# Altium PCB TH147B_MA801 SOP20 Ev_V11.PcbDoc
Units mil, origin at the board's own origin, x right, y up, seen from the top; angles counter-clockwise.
Board outline 2850 x 2110 mil, 2 copper layers (Top Layer, Bottom Layer); 44 components, 39 nets, 228 pads, 77 vias.
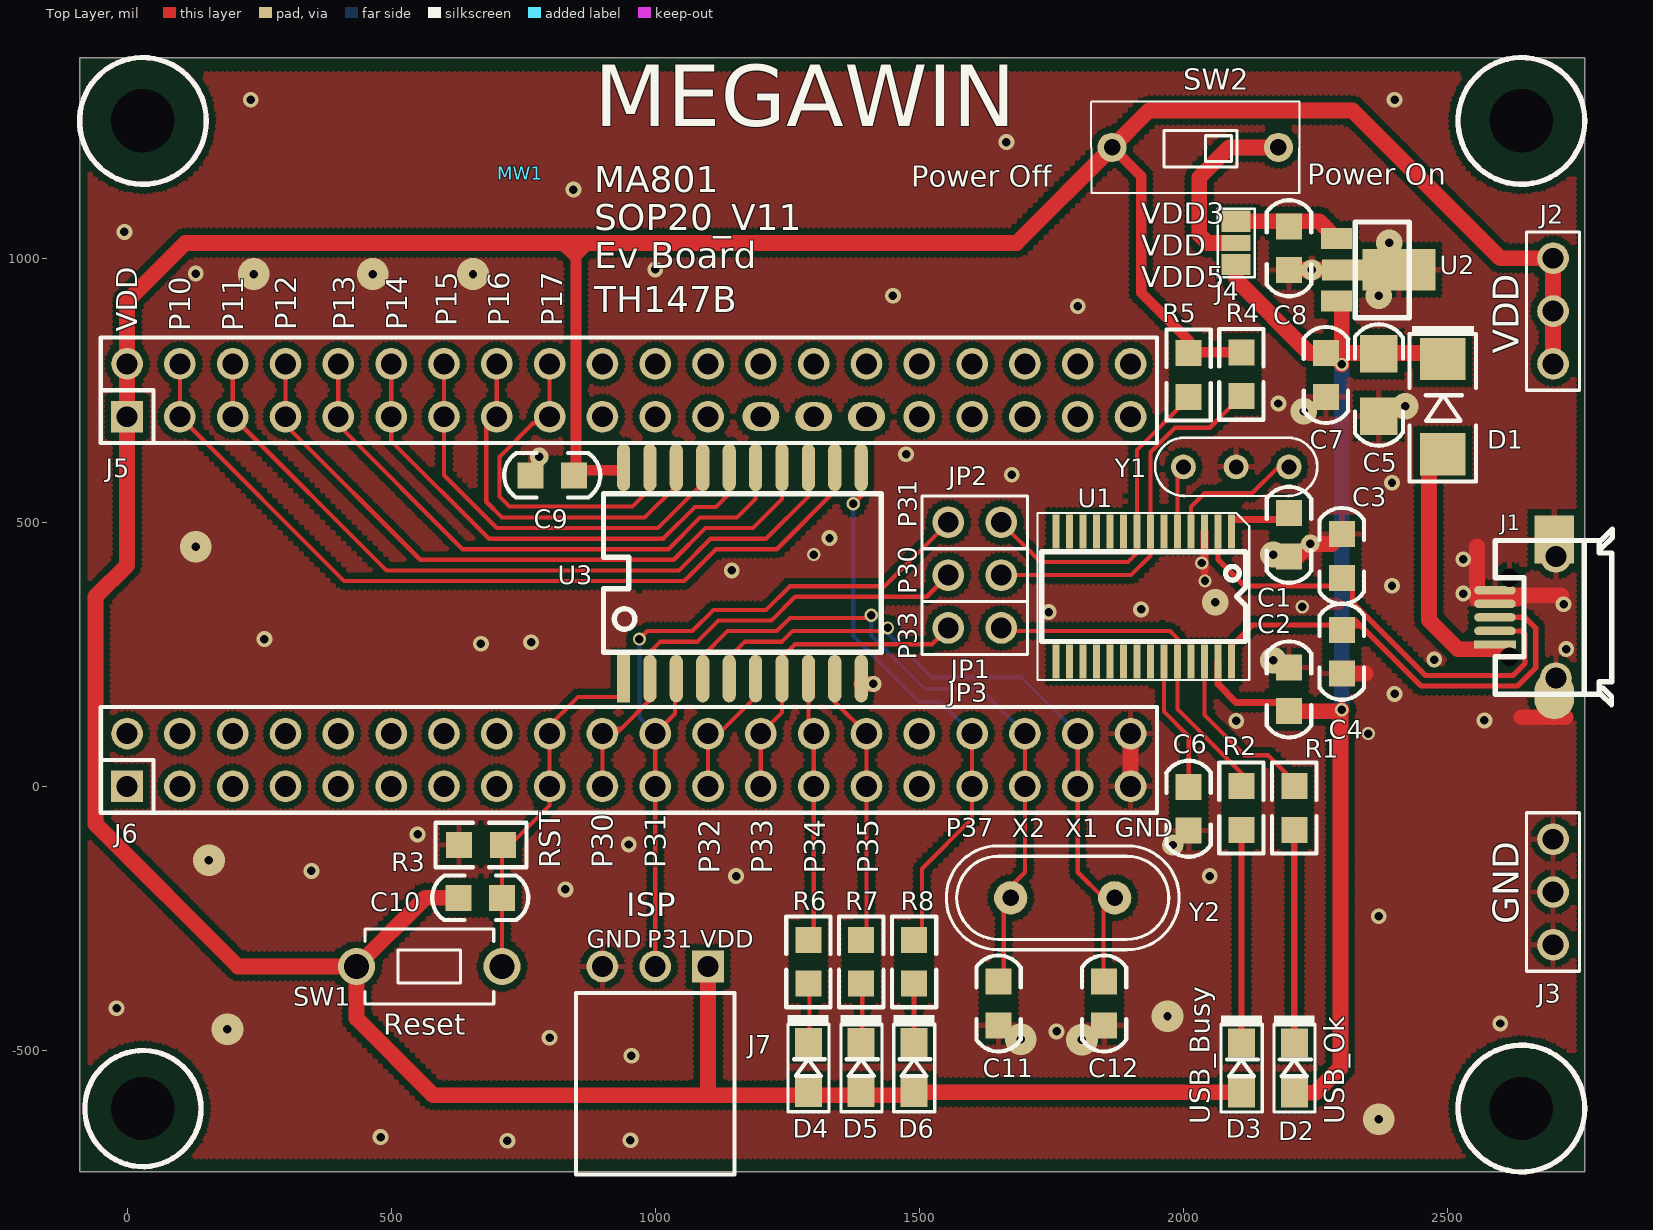
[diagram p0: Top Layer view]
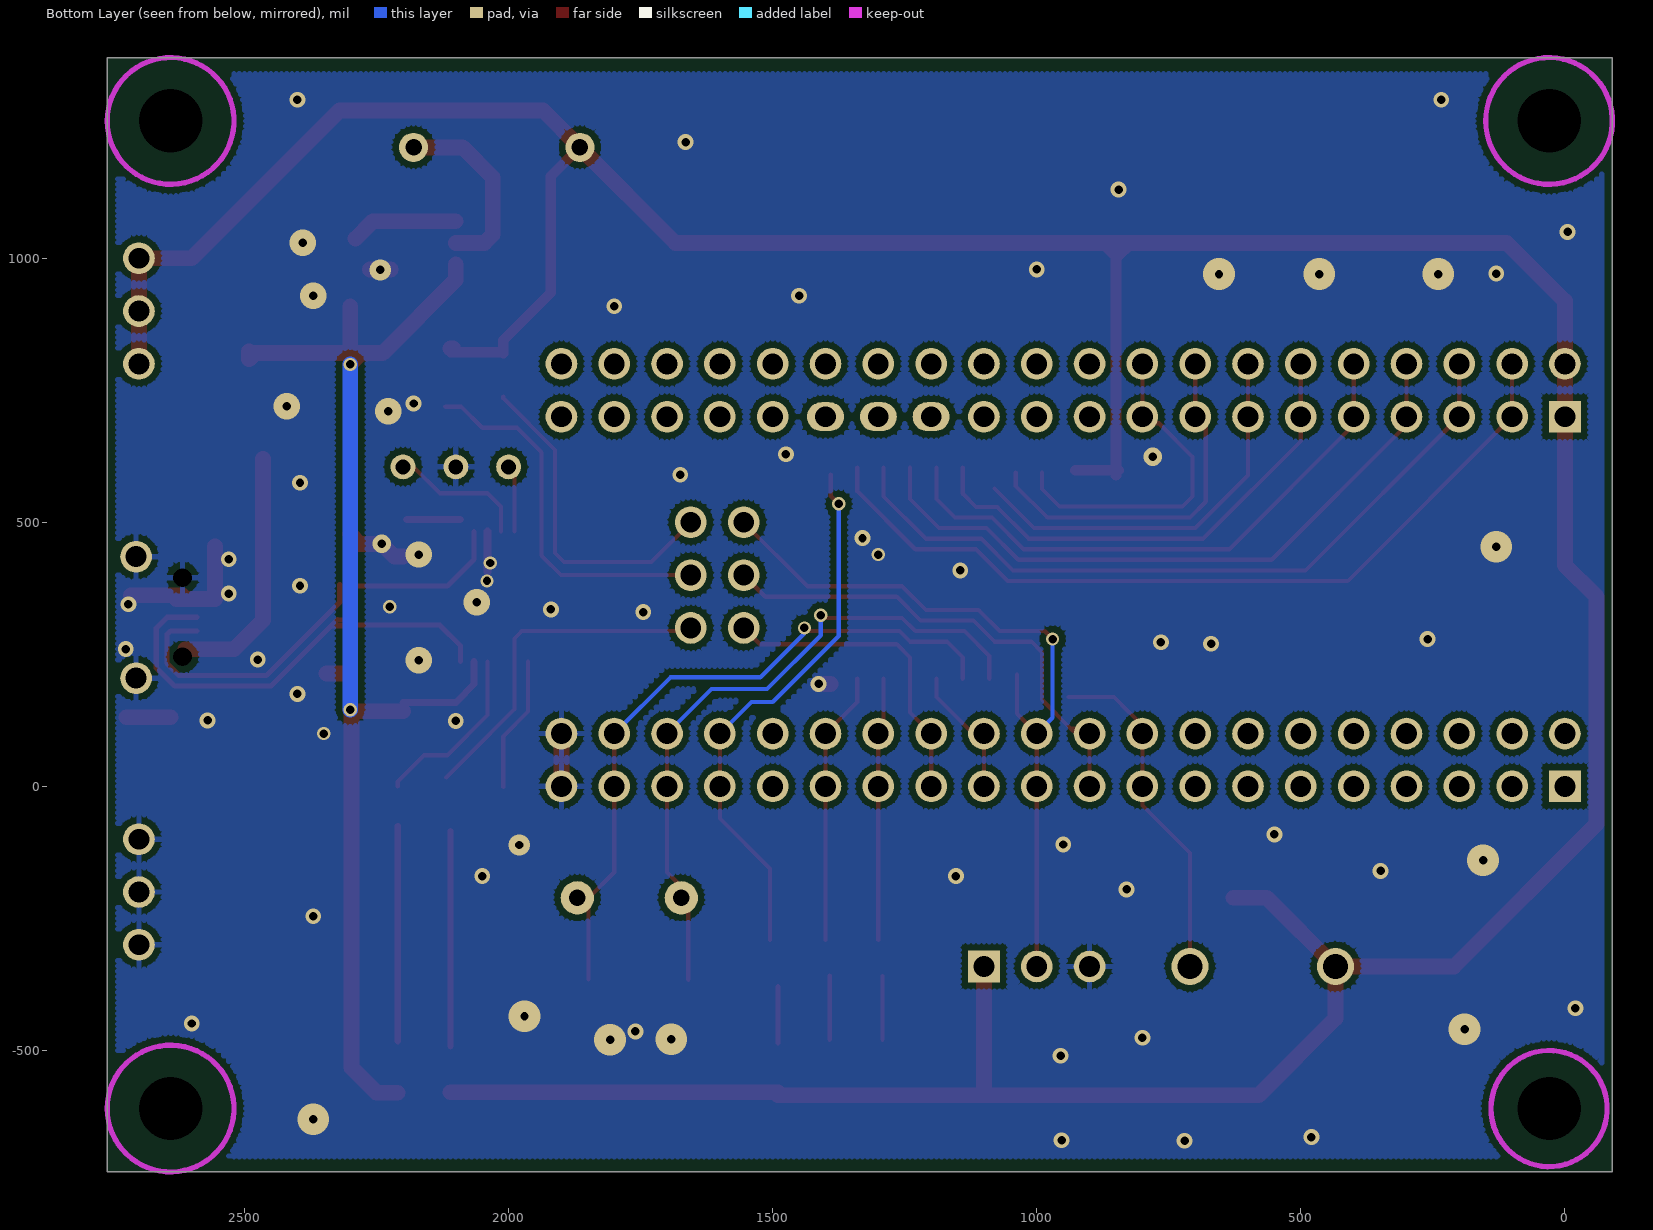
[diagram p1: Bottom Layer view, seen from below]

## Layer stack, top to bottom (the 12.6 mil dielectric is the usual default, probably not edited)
Top Layer: signal copper 1.4
Dielectric: dielectric 12.6, FR-4, Dk 4.8
Bottom Layer: signal copper 1.4

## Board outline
-90,-730 -90,1380 2760,1380 2760,-730

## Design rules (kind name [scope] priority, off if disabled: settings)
Clearance 12 [All] p1 off: gap=12
Clearance 10 [All] p2 off: gap=10
Clearance 6 [All] p3: gap=6
ComponentClearance [All] p1 off: gap=10 collisioncheckmode=3 verticalgap=10 showdistances=FALSE
HoleSize [All] p1: absolutevalues=TRUE maxlimit=500 minlimit=1 maxpercent=80.000 minpercent=20.000
MinimumSolderMaskSliver [All] p1 off: minsoldermaskwidth=10
PolygonConnect VIA [ISVIA] p1: connectstyle=Direct reliefconductorwidth=10 reliefentries=4 polygonreliefangle="90 Angle"
PolygonConnect [All] p2: connectstyle=Relief reliefconductorwidth=10 reliefentries=4 polygonreliefangle="90 Angle"
RoutingVias [All] p1: holewidth=16 width=25 viastyle="Through Hole" minholewidth=16 minwidth=24 maxholewidth=28 maxwidth=50
SilkToSilkClearance [All] p1 off: silktosilkclearance=10
SilkscreenOverComponentPads [All] p1 off: minsilkscreentomaskgap=10
SolderMaskExpansion [All] p1 off: expansion=4
Width [All] p1: maxlimit=200 minlimit=6 preferedwidth=10
23 further rules are at their usual default settings.

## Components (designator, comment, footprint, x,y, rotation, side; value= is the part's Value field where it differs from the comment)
C1 "4.7uF" 0805C 2200,476.34 r270 top
C2 "0.1uF" 0805C 2200,183.66 r270 top
C3 "15pF" 0805C 2300,436.34 r90 top
C4 "15pF" 0805C 2300,255 r270 top
C5 "4.7uF" 1206C 2370,760 r270 top
C6 "0.1uF" 0805C 2010,-42.34 r90 top
C7 "0.1uF" 0805C 2270,779 r270 top
C8 "4.7uF" 0805C 2200,1019 r270 top
C9 "0.1uF" 0805C 805,589 r180 top
C10 "1u" 0805C 668.66,-211 r0 top
C11 "30p" 0805C 1650,-411 r270 top
C12 "30p" 0805C 1850,-411 r270 top
D1 "1N5817" D5817_SMD_1 2491.34,719 r270 top
D2 "Yellow" 0805D 2210,-533.08 r90 top
D3 "RED" 0805D 2110,-533.08 r90 top
D4 "Green" 0805D 1290,-532.34 r90 top
D5 "RED" 0805D 1390,-532.34 r90 top
D6 "Green" 0805D 1490,-532.34 r90 top
J1 "Micro USB母座" JACK_USB_SMD290X220P065 2590,320 r180 top
J2 "*" PS3P254 2700,800 r90 top
J3 "*" PS3P254 2700,-100 r270 top
J4 "*" JUMP3_SMD 2100,1029 r90 top
J5 "*" PS20X2P254#1 0,700 r0 top locked
J6 "*" PS20X2P254#2 0,0 r0 top locked
J7 "*" PS3P254f_90 1100,-341 r180 top
JP1 "JUMPER2" PS2P254 1555,400 r0 top
JP2 "JUMPER2" PS2P254 1555,500 r0 top
JP3 "JUMPER2" PS2P254 1555,300 r0 top
MW1 "MW-A4" MEGAWIN_T 744.19,1161.19 r0 top
R1 "1K" 0805R 2210,-41 r270 top
R2 "1K" 0805R 2110,-41 r270 top
R3 "47K" 0805R 670,-111 r0 top
R4 "4.7K" 0805R 2110,780.34 r270 top
R5 "4.7K" 0805R 2010,779 r270 top
R6 "1K" 0805R 1290,-332.34 r270 top
R7 "1K" 0805R 1390,-332.34 r270 top
R8 "1K" 0805R 1490,-332.34 r270 top
SW1 "SW TACT-SPST" SW_T_2P 572.21,-341 r180 top
SW2 "-" DIP2_SW 2180,1210 r180 top
U1 "MA101_TSSOP28" TSSOP28_170P065 1924.84,359.52 r180 top
U2 "AIC1734-33(SOT-89)" SOT89 2290,978.06 r270 top
U3 "MA801 (20-SOP)" SO20_300P127 1165,404 r0 top locked
Y1 "6MHz" X3P 2200,605 r180 top
Y2 "22.1184MHz" X49U 1771.57,-211 r0 top

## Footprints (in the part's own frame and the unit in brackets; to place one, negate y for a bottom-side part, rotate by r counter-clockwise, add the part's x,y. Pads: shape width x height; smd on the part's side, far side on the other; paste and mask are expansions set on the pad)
0805C [mm]
  rect 1.25x1.25 smd: 1(-1.05,0) 2(1.05,0)
  silkscreen extent -2.31,-1.07 2.31,1.07
0805D [mm]
  rect 1.4x1.3 smd: 1(-1.192,0) 2(1.192,0)
  silkscreen extent -2.12,-1 2.53,0.98
0805R [mm]
  rect 1.25x1.25 smd: 1(-1.05,0) 2(1.05,0)
  silkscreen extent -2.18,-1.07 2.18,1.07
1206C [mm]
  rect 1.8x1.8 smd: 1(-1.5,0) 2(1.5,0)
  silkscreen extent -2.92,-1.15 2.92,1.16
D5817_SMD_1 [mil]
  rect 80x86.61 smd: 1(90,0) 2(-90,0)
  silkscreen extent -153,-63 142,63
DIP2_SW [mm]
  round 1.4 hole 0.8: 1(0,0) 2(8,0)
  silkscreen extent -1.02,-2.2 9.02,2.2
JACK_USB_SMD290X220P065 [mm]
  rect 1.9x1.8 on Mech2: 0(-2.85,-1.15) 0(-2.85,1.15)
  round 0.8 hole 0.9 unplated: 1(-0.7,1.9) 5(-0.7,-1.9)
  rect 2x0.4 smd: 1(0,1.3)
  oval 2x0.4 smd: 2(0,0.65) 3(0,0) 4(0,-0.65) 5(0,-1.3)
  round 1.524 hole 1: 5(-2.931,2.921) 5(-2.931,-2.921)
  oval 1.9x2.3 smd: 5(-2.85,3.75)
  rect 1.9x2.3 smd: 5(-2.85,-3.75)
  silkscreen extent -5.65,-4.25 -0.01,4.2
JUMP3_SMD [mil]
  rect 40x55 smd: 1(-41,0) 3(41,0)
  rect 30x55 smd: 2(0,0)
  silkscreen extent -65,-35 65,35
MEGAWIN_T [mil]
PS2P254 [mil]
  round 60 hole 39.37: 1(0,0) 2(100,0)
  silkscreen extent -50,-50 150,50
PS3P254 [mil]
  round 60 hole 39.37: 1(0,0) 2(100,0) 3(200,0)
  silkscreen extent -50,-50 250,50
PS3P254f_90 [mil]
  rect 60x60 hole 39.37: 1(0,0)
  round 60 hole 39.37: 2(100,0) 3(200,0)
  silkscreen extent -50,50 250,394
PS20X2P254#1 [mil]
  rect 60x60 hole 39.37: 1(0,0)
  round 60 hole 39.37: 2(0,100) 3(100,0) 4(100,100) 5(200,0) 6(200,100) 7(300,0) 8(300,100) 9(400,0) 10(400,100) 11(500,0) 12(500,100) 13(600,0) 14(600,100) 15(700,0) 16(700,100) 17(800,0) 18(800,100) 19(900,0) 20(900,100) 21(1000,0) 22(1000,100) 23(1100,0) 24(1100,100) 26(1200,100) 28(1300,100) 30(1400,100) 31(1500,0) 32(1500,100) 33(1600,0) 34(1600,100) 35(1700,0) 36(1700,100) 37(1800,0) 38(1800,100) 39(1900,0) 40(1900,100)
  oval 70x55 hole 39.37: 25(1200,0) 27(1300,0) 29(1400,0)
  silkscreen extent -50,-50 1950,150
PS20X2P254#2 [mil]
  rect 60x60 hole 39.37: 1(0,0)
  round 60 hole 39.37: 2(0,100) 3(100,0) 4(100,100) 5(200,0) 6(200,100) 7(300,0) 8(300,100) 9(400,0) 10(400,100) 11(500,0) 12(500,100) 13(600,0) 14(600,100) 15(700,0) 16(700,100) 17(800,0) 18(800,100) 19(900,0) 20(900,100) 21(1000,0) 22(1000,100) 23(1100,0) 24(1100,100) 25(1200,0) 26(1200,100) 27(1300,0) 28(1300,100) 29(1400,0) 30(1400,100) 31(1500,0) 32(1500,100) 33(1600,0) 34(1600,100) 35(1700,0) 36(1700,100) 37(1800,0) 38(1800,100) 39(1900,0) 40(1900,100)
  silkscreen extent -50,-50 1950,150
SO20_300P127 [mil]
  rect 25x90 smd: 1(-225,-200)
  oval 25x90 smd: 2(-175,-200) 3(-125,-200) 4(-75,-200) 5(-25,-200) 6(25,-200) 7(75,-200) 8(125,-200) 9(175,-200) 10(225,-200) 11(225,200) 12(175,200) 13(125,200) 14(75,200) 15(25,200) 16(-25,200) 17(-75,200) 18(-125,200) 19(-175,200) 20(-225,200)
  silkscreen extent -263,-150 263,150
SOT89 [mm]
  rect 1.016x1.5 smd: 1(-1.5,0) 3(1.5,0)
  rect 2x3.5 smd: 2(0,3)
  rect 1.016x2.6 smd: 2(0,0.6)
  silkscreen extent -2.3,0.9 2.3,3.5
SW_T_2P [mil]
  round 70 hole 47.24: 1(-137.79,0) 2(137.79,0)
  silkscreen extent -122,-71 122,71
TSSOP28_170P065 [mil]
  rect 13x65 smd: 1(-166.34,-123) 2(-140.75,-123) 3(-115.16,-123) 4(-89.57,-123) 5(-63.98,-123) 6(-38.39,-123) 7(-12.79,-123) 8(12.8,-123) 9(38.39,-123) 10(63.98,-123) 11(89.57,-123) 12(115.16,-123) 13(140.75,-123) 14(166.34,-123) 15(166.34,123) 16(140.75,123) 17(115.16,123) 18(89.57,123) 19(63.98,123) 20(38.39,123) 21(12.8,123) 22(-12.79,123) 23(-38.39,123) 24(-63.98,123) 25(-89.57,123) 26(-115.16,123) 27(-140.75,123) 28(-166.34,123)
  silkscreen extent -200,-158 201,158
X3P [mm]
  round 1.2 hole 0.711: 1(0,0) 2(5.08,0) 3(2.54,0)
  silkscreen extent -1.36,-1.4 6.44,1.4
X49U [mm]
  round 1.6 hole 0.8: 1(-2.5,0) 2(2.5,0)
  silkscreen extent -5.6,-2.5 5.6,2.5

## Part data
C1 C5 C8: library part CAP
C2 C3 C4 C6 C7 C9: library part "CAP NP"
C10: library part C
C11 C12: library part "C NP"
D1: library part DIODE_ZD, "Schottky Diode"
D2 D3 D4 D5 D6: library part LED
J1: library part CON5, "Connector"
J2 J3 J4 J7: library part CON3
J5 J6: library part CON40A
R1 R2 R4 R5 R6 R7 R8: library part R_Dup1
R3: library part R
SW2: library part SW-2
U2: library part AIC1734-33(SOT-89)_0
U3: library part MPC82L52(20-DIP)
Y1: library part CRYSTAL_RC
Y2: library part CRYSTAL

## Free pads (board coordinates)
  round 40 hole 120 unplated: 0(30,-610) 0(30,1260) 0(2640,-610) 0(2640,1260)

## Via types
v1: diameter 30, hole 16, Top Layer to Bottom Layer, tented both sides, 45 vias
v2: diameter 25, hole 16, Top Layer to Bottom Layer, tented both sides, 11 vias
v3: diameter 60, hole 16, Top Layer to Bottom Layer, tented both sides, 10 vias
v4: diameter 50, hole 16, Top Layer to Bottom Layer, tented both sides, 7 vias
v5: diameter 35, hole 16, Top Layer to Bottom Layer, tented both sides, 2 vias
v6: diameter 40, hole 16, Top Layer to Bottom Layer, tented both sides, 2 vias

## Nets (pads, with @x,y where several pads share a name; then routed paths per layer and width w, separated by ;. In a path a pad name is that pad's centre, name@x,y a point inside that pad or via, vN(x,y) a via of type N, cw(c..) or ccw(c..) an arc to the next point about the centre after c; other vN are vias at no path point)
D+: C4.1 J1.3 U1.28 | length 868.9
  Top Layer w10: U1.28 2091.18,266.18 2130.67,305.67 C4.1@2300,305.67 ; C4.1@2299,304 2332.72,304 ; C4.1@2315,315 2325,315 ; C4.1@2324,316 2325,315 ; J1.3 2646.93,320 2667,299.93 2667,224.28 2632.72,190 2450,190 2325,315
D-: C3.1 J1.2 U1.2 | length 850.6
  Top Layer w10: U1.2 2065.59,429.41 2115.63,379.37 C3.1@2300,379.37 ; C3.1@2320,382 2320,348.28 2458.28,210 2624.44,210 2647,232.56 2647,287.84 2640.43,294.41 J1.2
GND_POWER: C1.2 C2.1 C3.2 C4.2 C5.2 C6.1 C7.2 C8.2 C9.2 C11.2 C12.2 J1.4 J1.5 J3.1 J3.2 J3.3 J6.39 J6.40 J7.3 R3.1 U1.3 U2.2 U3.10 Y1.3 | length 754.1
  Top Layer w15: 2040,406 v2@2040,416 ; U1.3 v2@2040,416 ; v2@2041,415 v2@2040,416
  Top Layer w30: U3.10@1390,194 v1(1413,194) ; J6.39 J6.40 ; C1.2 2216,435 v5(2240,459) 2281.32,459 C3.2 ; C8.2@2223.34,979 U2.2@2263,979 ; C4.2 2344.66,213.66 ; 2555.87,355.05 2629.29,355.05 ; 2555.87,357.64 2555.87,454.72 ; 2618.54,362.05 2715.63,362.05 ; 2640.28,130.87 2723.82,130.87
  other v1: 720,-671 953,-670 480,-664 955,-510 800,-476 1760,-464 2600,-449 -20,-420 2370,-246 830,-195 1153,-170 2050,-170 349,-160 950,-110 550,-91 2100,124 2570,125 2400,175 2475,240 2725,260 670,270 765,273 260,279 1745,330 1920,335 2720,345 2530,365 2395,380 1145,409 2530,430 1330,470 2395,575 1675,590 1475,629 2180,725 1800,909 1450,929 130,971 1000,979 -5,1050 845,1130 1665,1220 234,1300 2400,1300
  other v2: 2350,100 2225,340 2041,389 2035,423 1300,439
  other v3: 2370,-630 1808,-479.5 1692,-478.83 190,-460 1970,-435 155,-140 130,454 240,970 465,970 655,970
  other v4: 2170,239 2060,349 2170,439 2228,710.5 2420,720 2370,929 2390,1029
  other v5: 780,624
  other v6: 1980,-111 2243,978
MA101_RX: JP2.2 R5.2 U1.8 | length 631.4
  Top Layer w8: JP2.2 1730,425 1895,425 1912.05,442.05 U1.8 1912.05,637.05 2010,735 R5.2
MA101_TX: JP1.2 R4.2 U1.7 | length 711.9
  Top Layer w8: JP1.2 1901,400 1937.64,436.64 1937.64,632.64 1984,679 2050,679 2090,719 R4.2@2120,719
NetC1_1: C1.1 U1.1 | length 102.5
  Top Layer w13: U1.1@2091.18,505 C1.1@2193.66,505
NetC6_2: C6.2 U1.23 | length 269.1
  Top Layer w8: 1963.23,191.18 1963.23,179 ; U1.23 1963.23,179 ; C6.2 2010,95 1963.23,141.77 1963.23,179
NetD1_1: D1.1 J1.1 | length 475.3
  Top Layer w30: D1.1@2465,620 2465,314.72 2520,259.72 J1.1@2612.2,259.72
NetD2_2: D2.2 R1.2 | length 407.7
  Top Layer w12: D2.2@2210,-482.66 R1.2 R1.2@2210,-75
NetD3_2: D3.2 R2.2 | length 407.7
  Top Layer w12: D3.2@2110,-492.66 D3.2 R2.2@2110,-85
NetD4_2: D4.2 R6.2 | length 120.4
  Top Layer w8: D4.2@1292,-479.67 R6.2@1292,-359.27
NetD5_2: D5.2 R7.2 | length 121.7
  Top Layer w8: D5.2@1392,-479.67 R7.2@1392,-357.93
NetD6_2: D6.2 R8.2 | length 106
  Top Layer w10: D6.2 R8.2@1490,-379.43
NetJ4_2: J4.2 SW2.1 | length 358.1
  Top Layer w30: J4.2 2046,1029 2030,1045 2030,1152.83 2087.17,1210 SW2.1
NetU1_4: U1.4 Y1.1 | length 263.8
  Top Layer w8: U1.4 2014.41,529.41 2040,555 2130,555 2180,605 Y1.1
NetU1_5: U1.5 Y1.2 | length 127.1
  Top Layer w8: U1.5 1988.82,593.82 Y1.2
P10: J5.3 J5.4 U3.12 | length 1584.2
  Top Layer w8: J5.4 J5.3 411,389 1055,389 1115,449 1230,449 1340,559 U3.12
P11: J5.5 J5.6 U3.13 | length 1423.5
  Top Layer w8: J5.6 J5.5 491,409 1045,409 1105,469 1210,469 1290,549 U3.13
P12: J5.7 J5.8 U3.14 | length 1269.3
  Top Layer w8: J5.8 J5.7 300,684 555,429 1035,429 1095,489 1185,489 1240,544 U3.14
P13: J5.9 J5.10 U3.15 | length 1102.7
  Top Layer w8: J5.10 J5.9 400,684 635,449 1025,449 1085,509 1155,509 1190,544 U3.15
P14: J5.11 J5.12 U3.16 | length 947.8
  Top Layer w8: J5.12 J5.11 500,654 685,469 1015,469 1075,529 1115,529 1140,554 U3.16
P15: J5.13 J5.14 U3.17 | length 763.5
  Top Layer w8: J5.14 J5.13 600,589 700,489 1005,489 1080,564
P16: J5.15 J5.16 U3.18 | length 718.2
  Top Layer w8: J5.15 J5.15@700,709 ; J5.16 J5.15@700,709 ; J5.15@712.5,687.5 J5.15@725,700 ; U3.18@1040,594 1040,569 980,509 710,509 680,539 680,689 J5.15@700,709
P17: J5.17 J5.18 U3.19 | length 664
  Top Layer w8: J5.17 J5.18 ; J5.17@825,700 812.5,687.5 768.5,687.5 705,624 705,549 724,530 957,530 990,563 U3.19@990,594
P30_RXD: J6.19 J6.20 JP1.1 U3.2 | length 961.9
  Top Layer w8: J6.19 J6.20 J6.20@911,100 ; J6.20@905,105 931,105 935,109 ; J6.20@909,109 935,109 ; JP1.1 1514,359 1265,359 1220,314 1120,314 1080,274 1010,274 990,254 U3.2 990,164 935,109
P31_TXD: J6.21 J6.22 J7.2 JP2.1 U3.3 | length 1541.1
  Top Layer w8: v2(970,279) 985,294 1070,294 1110,334 1210,334 1255,379 1434,379 JP2.1 ; 1000,-236 J7.2 J6.21 J6.22 1037.6,137.6 U3.3@1037.6,211.6
  Bottom Layer w8: v2(970,279) 970,130 J6.22
P32: J6.23 J6.24 U3.6 | length 264.6
  Top Layer w8: J6.23 J6.24 ; J6.24@1111,100 J6.24 ; U3.6 1190,169 1121,100 J6.24
P33: J6.25 J6.26 JP3.1 U3.7 | length 599.8
  Top Layer w8: J6.25 J6.26 1240,140 U3.7 1240,244 1265,269 1524,269 JP3.1 ; J6.26@1220,99 J6.26@1220,100
P34: J6.27 J6.28 R6.1 U3.8 | length 565
  Top Layer w8: J6.28@1290,99 U3.8 1290,135 ; R6.1@1300,-291 J6.27 J6.28
P35: J6.29 J6.30 R7.1 U3.9 | length 539.9
  Top Layer w8: U3.9 1340,160 J6.30 ; J6.30@1380,100 J6.30 ; R7.1@1400,-291 J6.29 J6.30
P37: J6.33 J6.34 R8.1 U3.11 | length 1052.2
  Top Layer w8: v2(1375,535) 1390,550 U3.11@1390,590 ; R8.1@1505,-291 1505,-156 1600,-61 J6.33 J6.34 J6.34@1600,109
  Bottom Layer w8: v2(1375,535) 1375,285 1500,160 1540,160 J6.34
RST: C10.2 J6.17 J6.18 R3.2 SW1.1 U3.1 | length 696.7
  Top Layer w8: SW1.1 C10.2 710,-126 800,-36 J6.17 J6.18 800,115 854,169 ; 825,140 854,169 ; U3.1@940,169 854,169
USB_BUSY: JP3.2 R2.1 U1.24 | length 855.2
  Top Layer w8: JP3.2@1655,294 1780,294 ; 1710,294 1780,294 ; 2080,55 1988.82,146.18 ; R2.1@2118,17 1988.82,146.18 ; 1780,294 1975,294 1988.82,280.18 U1.24 1988.82,146.18
USB_OK: R1.1 U1.26 | length 344.6
  Top Layer w8: 2040,191.18 2040,179 ; U1.26 2040,179 ; R1.1 2210,9 2160,59 2116,59 2040,135 2040,179
VDD: C9.1 C10.1 D3.1 D4.1 D5.1 D6.1 J2.1 J2.2 J2.3 J5.1 J5.2 J7.1 R4.1 R5.1 SW1.2 SW2.2 U3.20 | length 8323.9
  Top Layer w15: 780,1029 785,1034 ; 817,1029 848.5,997.5 ; 850,999 880,1029
  Top Layer w20: C9.1@845,599 C9.1@850,599 ; C9.1@850,589 C9.1@850,599 ; 850,1029 850,999 C9.1@850,599 ; 927,599 C9.1@850,599 ; 1555.04,1030 1556.04,1029 ; SW2.2 1920,1155.04 1920,935 2010,845 R5.1 ; R5.1@2011.34,821.68 R4.1
  Top Layer w30: 0,465 0,479 ; C10.1 564.41,-211 SW1.2 ; J7.1 1100,-584.9 ; 1417.56,-584.9 D5.1@1390,-584.9 ; D6.1@1490,-584.9 D5.1@1390,-584.9 ; D6.1 D3.1@2110,-579.26 ; R4.1@2104.95,829 R4.1@2110,829 ; J2.1 J2.2 J2.3 2600,1000 2320,1280 1935.04,1280 SW2.2 1684.04,1029 1556.04,1029 880,1029 850,1029 817,1029 780,1029 110,1029 0,919 J5.2 J5.1 0,479 ; 0,479 0,419 -60,359 -60,-71 210,-341 SW1.2 ; SW1.2 434.41,-439.31 580,-584.9 1100,-584.9 ; 1100,-584.9 D5.1@1390,-584.9
VDD3: C8.1 J4.3 U2.1 | length 203.6
  Top Layer w30: J4.3 2257.11,1070 U2.1
VDD5: C2.2 C5.1 C7.1 D1.2 D2.1 J4.1 U1.27 U2.3 | length 2345.5
  Top Layer w13: U1.27 2065.59,193.41 2100,159 C2.2@2200,159
  Top Layer w30: J4.1 2100,959 2238.66,820.34 C7.1@2268.66,820.34 ; C2.2 v2@2297.32,142.32 ; D2.1 2250,-580 2297.32,-532.68 v2@2297.32,142.32 ; C7.1@2269.33,819.67 C7.1@2268.66,820.34 ; v2(2300,145) v2@2297.32,142.32 ; v2(2300,799) 2300,800.34 C7.1@2280,820.34 ; U2.3@2300,909 2300,820.34 ; D1.2@2491.34,823.96 D1.2 2480,820.34 2300,820.34 ; C7.1@2268.66,820.34 C7.1 C7.1@2280,820.34 ; C7.1@2280,820.34 2300,820.34
  Bottom Layer w30: v2(2300,145) v2(2300,799)
XTAL1: C12.1 J6.37 J6.38 U3.5 Y2.2 | length 1294.6
  Top Layer w8: U3.5 1140,244 1170,274 1240,274 1260,294 v2@1440,294 ; J6.38 J6.37 1800,-162.58 1848.66,-211.24 C12.1@1848.66,-365
  Bottom Layer w8: v2(1440,300) 1440,290 1523.5,206.5 1693.5,206.5 J6.38
XTAL2: C11.1 J6.35 J6.36 U3.4 Y2.1 | length 1266.8
  Top Layer w8: U3.4 1090,247 1137,294 1230,294 1255,319 v2@1409,319 ; C11.1@1660,-366 Y2.1@1660,-212.85 ; Y2.1@1662.36,-200.21 1700,-162.58 J6.35 J6.36
  Bottom Layer w8: v2(1409,324) 1409,286 1510.71,184.29 1615.71,184.29 J6.36
pads on no net: J1.0 J5.19 J5.20 J5.21 J5.22 J5.23 J5.24 J5.25 J5.26 J5.27 J5.28 J5.29 J5.30 J5.31 J5.32 J5.33 J5.34 J5.35 J5.36 J5.37 J5.38 J5.39 J5.40 J6.1 J6.2 J6.3 J6.4 J6.5 J6.6 J6.7 J6.8 J6.9 J6.10 J6.11 J6.12 J6.13 J6.14 J6.15 J6.16 J6.31 J6.32 U1.6 U1.9 U1.10 U1.11 U1.12 U1.13 U1.14 U1.15 U1.16 U1.17 U1.18 U1.19 U1.20 U1.21 U1.22 U1.25

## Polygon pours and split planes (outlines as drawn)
GND_POWER on Top Layer "Bottom Layer-No Net" (hatched 90Degree grid 10 track 10, remove dead copper, pour order 1001): -70,-701 2740,-701 2740,1350 -70,1350
GND_POWER on Bottom Layer "Bottom Layer-No Net" (hatched 90Degree grid 10 track 10, remove dead copper, pour order 1001): -70,-701 2740,-701 2740,1350 -70,1350

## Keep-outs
Keep-Out Layer:
  circle w10: c2640,1260 r120
  circle w10: c30,-610 r110
  circle w10: c30,1260 r120
  circle w10: c2640,-610 r120

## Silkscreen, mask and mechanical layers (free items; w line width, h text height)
Top Overlay:
  circle w10: c2640,1260 r120
  circle w10: c30,-610 r110
  circle w10: c30,1260 r120
  circle w10: c2640,-610 r120
  text "Power On" at 2235,1139 h40
  text "Power Off" at 1485,1135 h40
  text "MA801" at 884.19,1125.19 h50
  text "VDD3" at 1920,1065 h40
  text "SOP20_V11" at 885,1053 h50
  text "VDD" at 1920,1005 h40
  text "Ev Board" at 885,981 h50
  text "VDD5" at 1920,945 h40
  text "TH147B" at 885,898 h50
  text "P15" at 623.95,870.95 h40 r90
  text "P16" at 723.95,870.95 h40 r90
  text "P17" at 823.95,870.95 h40 r90
  text "P12" at 320,864 h40 r90
  text "P13" at 430,864 h40 r90
  text "P14" at 530,864 h40 r90
  text "P10" at 120,862 h40 r90
  text "P11" at 220,862 h40 r90
  text "VDD" at 19,861 h40 r90
  text "VDD" at 2635,819 h50 r90
  text "P31" at 1495,490 h35 r90
  text "P30" at 1495,364 h35 r90
  text "P33" at 1495,240 h35 r90
  text "P37" at 1550,-95 h35
  text "GND" at 1870,-95 h35.43
  text "X2" at 1675,-96 h35
  text "X1" at 1775,-96 h35.43
  text "RST" at 820,-155 h40 r90
  text "P30" at 920,-155 h40 r90
  text "P31" at 1020,-155 h40 r90
  text "P32" at 1122,-165 h40 r90
  text "P33" at 1222,-165 h40 r90
  text "P34" at 1322,-165 h40 r90
  text "P35" at 1422,-165 h40 r90
  text "ISP" at 945,-246 h45
  text "GND" at 2635,-261 h50 r90
  text "GND" at 870,-306 h33
  text "P31" at 985,-306 h33
  text "VDD" at 1085,-306 h33
  text "Reset" at 485,-470 h40
  text "USB_Busy" at 2050,-640 h38 r90
  text "USB_Ok" at 2305,-640 h38 r90
Mechanical 1:
  the board outline again, w13

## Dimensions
-90,-730 to 2760,-730 on Top Overlay
-90,1380 to -90,-730 on Top Overlay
